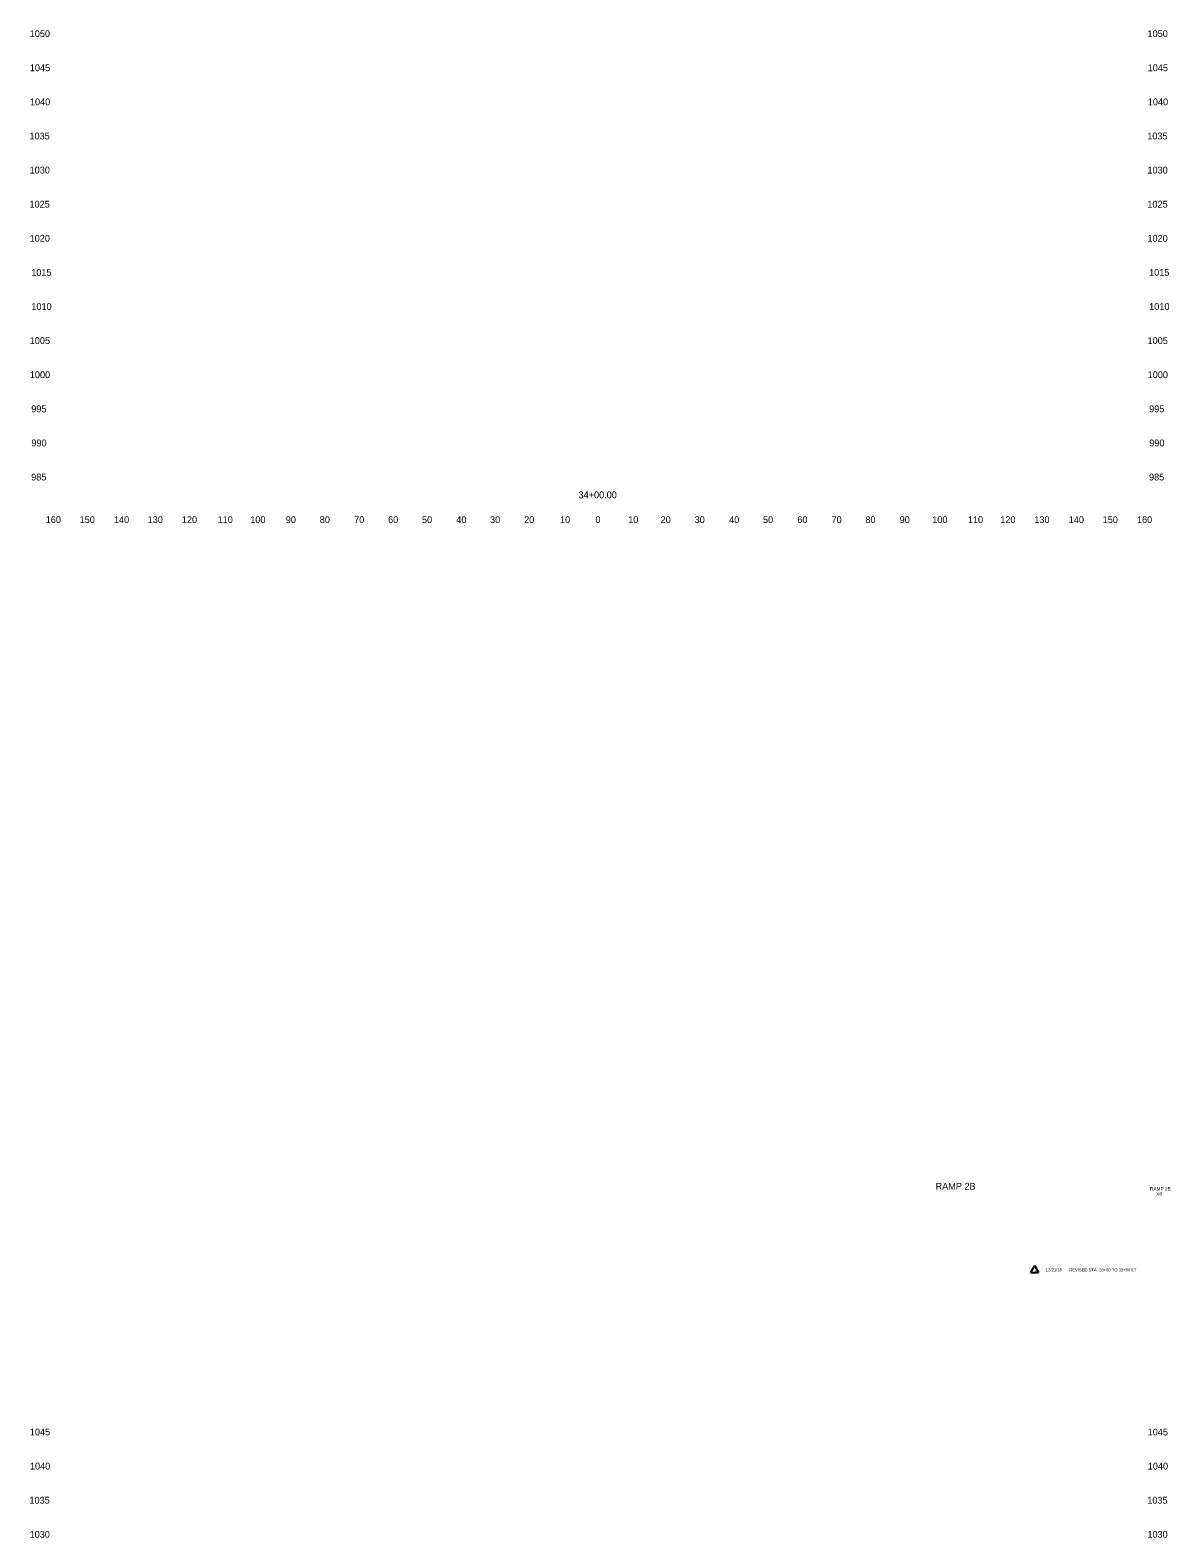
# Model space of a CAD drawing. Extents: x 4994 to 6358, y 4997 to 8804.
# Drawn here: x 4993.5 to 5327.7, y 7900 to 8342 of the extents above; entities that cross this region are included whole.
import ezdxf

# ---------------------------------------------------------------- set-up
doc = ezdxf.new("R2010")
doc.units = 0
for name, color, linetype in [('RD_SHT_ID', 7, 'Continuous'), ('RD_SHT_TX', 7, 'Continuous'), ('RD_XS_TX_Offset', 7, 'Continuous'), ('RD_XS_TX_Station', 7, 'Continuous')]:
    doc.layers.add(name, color=color, linetype=linetype)

msp = doc.modelspace()

# ---------------------------------------------------------------- linework, layer by layer
at = {"layer": 'RD_SHT_TX'}
for p, q in [((5288.05, 7979.83), (5286.91, 7977.8)), ((5288.05, 7979.83), (5289.19, 7977.8)), ((5286.91, 7977.8), (5289.19, 7977.8))]:
    msp.add_line(p, q, dxfattribs=at)

# ---------------------------------------------------------------- texts
at = {"layer": 'RD_SHT_ID'}
for s, height, p in [('RAMP 2B', 2, (5259.05, 8002.06)), ('RAMP 2B', 1, (5321.94, 8001.8)), ('X8', 1, (5323.74, 8000.3))]:
    msp.add_text(s, height=height, dxfattribs=at).set_placement(p)
at = {"layer": 'RD_SHT_TX'}
for s, p in [('1', (5288.05, 7978.13)), ('12/21/18', (5291.35, 7978.12)), ('REVISED STA. 28+00 TO 33+00 LT', (5298.25, 7978.09))]:
    msp.add_text(s, height=0.88, dxfattribs=at).set_placement(p)
at = {"layer": 'RD_XS_TX_Offset'}
for s, p in [('1050', (4993.4, 8340)), ('1050', (5321.2, 8340)), ('1045', (4993.44, 8330)), ('1045', (5321.24, 8330)), ('1040', (4993.47, 8320)), ('1040', (5321.27, 8320)), ('1035', (4993.33, 8310)), ('1035', (5321.13, 8310)), ('1030', (4993.36, 8300)), ('1030', (5321.16, 8300)), ('1025', (4993.34, 8290)), ('1025', (5321.14, 8290)), ('1020', (4993.37, 8280)), ('1020', (5321.17, 8280)), ('1015', (4993.85, 8270)), ('1015', (5321.65, 8270)), ('1010', (4993.88, 8260)), ('1010', (5321.68, 8260)), ('1005', (4993.4, 8250)), ('1005', (5321.2, 8250)), ('1000', (4993.44, 8240)), ('1000', (5321.24, 8240)), ('995', (4993.86, 8230)), ('995', (5321.66, 8230)), ('990', (4993.89, 8220)), ('990', (5321.69, 8220)), ('985', (4993.83, 8210)), ('985', (5321.63, 8210)), ('160', (4998.1, 8197.5)), ('150', (5008.04, 8197.5)), ('140', (5018.1, 8197.5)), ('130', (5027.99, 8197.5)), ('120', (5038.01, 8197.5)), ('110', (5048.51, 8197.5)), ('100', (5058.07, 8197.5)), ('90', (5068.5, 8197.5)), ('80', (5078.46, 8197.5)), ('70', (5088.54, 8197.5)), ('60', (5098.5, 8197.5)), ('50', (5108.43, 8197.5)), ('40', (5118.5, 8197.5)), ('30', (5128.39, 8197.5)), ('20', (5138.4, 8197.5)), ('10', (5148.91, 8197.5)), ('0', (5159.3, 8197.5)), ('0', (5159.3, 8197.5)), ('10', (5168.91, 8197.5)), ('20', (5178.4, 8197.5)), ('30', (5188.39, 8197.5)), ('40', (5198.5, 8197.5)), ('50', (5208.43, 8197.5)), ('60', (5218.5, 8197.5)), ('70', (5228.54, 8197.5)), ('80', (5238.46, 8197.5)), ('90', (5248.5, 8197.5)), ('100', (5258.07, 8197.5)), ('110', (5268.51, 8197.5)), ('120', (5278.01, 8197.5)), ('130', (5287.99, 8197.5)), ('140', (5298.1, 8197.5)), ('150', (5308.04, 8197.5)), ('160', (5318.1, 8197.5)), ('1045', (4993.44, 7930)), ('1045', (5321.24, 7930)), ('1040', (4993.47, 7920)), ('1040', (5321.27, 7920)), ('1035', (4993.33, 7910)), ('1035', (5321.13, 7910)), ('1030', (4993.36, 7900)), ('1030', (5321.16, 7900))]:
    msp.add_text(s, height=2, dxfattribs=at).set_placement(p)
at = {"layer": 'RD_XS_TX_Station'}
msp.add_text('34+00.00', height=2, dxfattribs=at).set_placement((5154.34, 8204.79))

doc.saveas('drawing.dxf')
